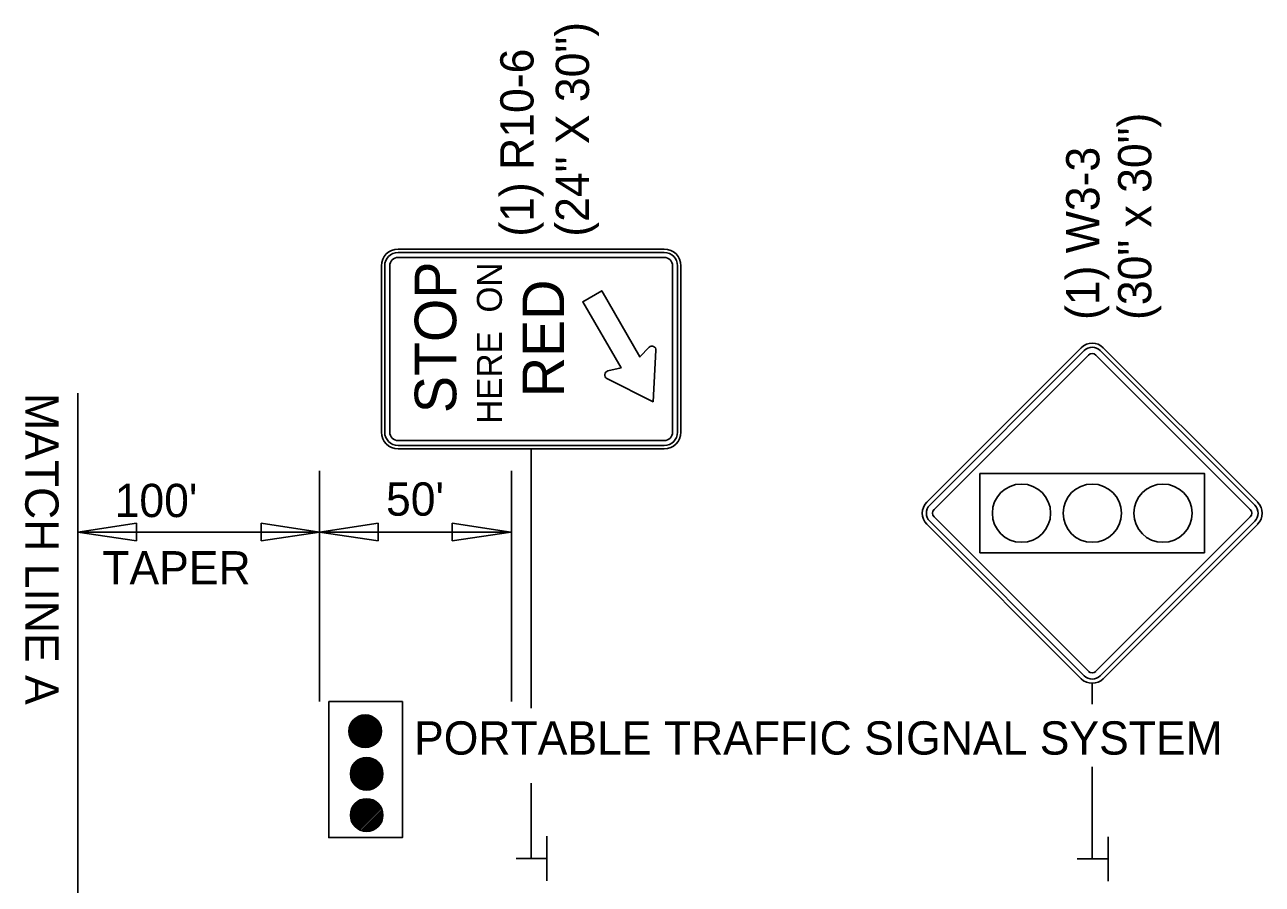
# Model space of a CAD drawing. Extents: x 1925873 to 1930787, y 596452 to 599617.
# Drawn here: x 1925900.5 to 1926123.6, y 596960 to 597114.9 of the extents above; entities that cross this region are included whole.
import ezdxf

# ---------------------------------------------------------------- set-up
doc = ezdxf.new("R2010")
doc.units = 0
for name, color, linetype in [('Default', 7, 'Continuous'), ('P_TC_Signs_Permanent', 7, 'Continuous'), ('R_Border', 7, 'Continuous')]:
    doc.layers.add(name, color=color, linetype=linetype)

msp = doc.modelspace()

# ---------------------------------------------------------------- linework, layer by layer
at = {"layer": 'Default'}
for p, q in [((1925910.09, 597048.55), (1925910.09, 596923.91)), ((1925953.65, 597034.54), (1925953.65, 596992.96)), ((1925988.22, 597034.54), (1925988.22, 596992.96)), ((1925910.09, 597023.5), (1925920.64, 597025.08)), ((1925920.64, 597025.08), (1925920.64, 597021.92)), ((1925943.11, 597021.92), (1925943.11, 597025.08)), ((1925943.11, 597025.08), (1925953.65, 597023.5)), ((1925953.65, 597023.5), (1925964.19, 597025.08)), ((1925964.19, 597025.08), (1925964.19, 597021.92)), ((1925977.56, 597021.92), (1925977.56, 597025.08)), ((1925977.56, 597025.08), (1925988.1, 597023.5)), ((1925920.64, 597021.92), (1925910.09, 597023.5)), ((1925910.09, 597023.5), (1925953.65, 597023.5)), ((1925953.65, 597023.5), (1925943.11, 597021.92)), ((1925953.65, 597023.5), (1925988.1, 597023.5)), ((1925964.19, 597021.92), (1925953.65, 597023.5)), ((1925988.1, 597023.5), (1925977.56, 597021.92)), ((1925958.92, 596987.65), (1925961.82, 596990.54)), ((1925958.93, 596987.47), (1925962, 596990.54)), ((1925958.93, 596987.84), (1925961.63, 596990.54)), ((1925958.94, 596987.3), (1925962.17, 596990.53)), ((1925958.96, 596987.14), (1925962.33, 596990.51)), ((1925958.96, 596988.04), (1925961.43, 596990.51)), ((1925958.99, 596986.99), (1925962.48, 596990.48)), ((1925959, 596988.26), (1925961.21, 596990.47)), ((1925959.02, 596986.84), (1925962.63, 596990.44)), ((1925959.06, 596986.7), (1925962.77, 596990.4)), ((1925959.07, 596988.51), (1925960.95, 596990.4)), ((1925959.11, 596986.57), (1925962.9, 596990.36)), ((1925959.16, 596986.44), (1925963.03, 596990.3)), ((1925959.18, 596988.81), (1925960.66, 596990.29)), ((1925959.22, 596986.31), (1925963.15, 596990.25)), ((1925959.28, 596986.2), (1925963.27, 596990.19)), ((1925959.35, 596986.08), (1925963.39, 596990.12)), ((1925959.4, 596989.21), (1925960.26, 596990.07)), ((1925959.42, 596985.97), (1925963.5, 596990.05)), ((1925959.49, 596985.86), (1925963.6, 596989.98)), ((1925959.57, 596985.76), (1925963.71, 596989.9)), ((1925959.65, 596985.66), (1925963.81, 596989.81)), ((1925959.74, 596985.57), (1925963.9, 596989.73)), ((1925959.83, 596985.48), (1925963.99, 596989.64)), ((1925959.93, 596985.39), (1925964.08, 596989.54)), ((1925960.02, 596985.31), (1925964.16, 596989.44)), ((1925960.13, 596985.23), (1925964.24, 596989.34)), ((1925960.23, 596985.16), (1925964.31, 596989.24)), ((1925960.34, 596985.09), (1925964.38, 596989.12)), ((1925960.46, 596985.02), (1925964.45, 596989.01)), ((1925960.58, 596984.96), (1925964.51, 596988.89)), ((1925960.7, 596984.9), (1925964.57, 596988.77)), ((1925960.83, 596984.85), (1925964.62, 596988.64)), ((1925960.96, 596984.8), (1925964.67, 596988.5)), ((1925961.1, 596984.76), (1925964.71, 596988.36)), ((1925961.25, 596984.73), (1925964.74, 596988.22)), ((1925961.4, 596984.7), (1925964.77, 596988.07)), ((1925961.56, 596984.68), (1925964.79, 596987.91)), ((1925961.73, 596984.66), (1925964.8, 596987.74)), ((1925961.91, 596984.66), (1925964.81, 596987.56)), ((1925962.1, 596984.67), (1925964.8, 596987.37)), ((1925962.3, 596984.69), (1925964.77, 596987.16)), ((1925962.53, 596984.74), (1925964.73, 596986.94)), ((1925962.78, 596984.81), (1925964.66, 596986.69)), ((1925963.07, 596984.92), (1925964.55, 596986.4)), ((1925963.47, 596985.14), (1925964.33, 596986)), ((1925959.19, 596979.99), (1925962.09, 596982.89)), ((1925959.2, 596979.81), (1925962.27, 596982.88)), ((1925959.2, 596980.18), (1925961.9, 596982.88)), ((1925959.21, 596979.64), (1925962.44, 596982.87)), ((1925959.23, 596979.48), (1925962.6, 596982.85)), ((1925959.23, 596980.38), (1925961.7, 596982.85)), ((1925959.26, 596979.33), (1925962.75, 596982.82)), ((1925959.27, 596980.6), (1925961.47, 596982.81)), ((1925959.29, 596979.18), (1925962.9, 596982.79)), ((1925959.33, 596979.04), (1925963.04, 596982.74)), ((1925959.34, 596980.85), (1925961.22, 596982.74)), ((1925959.38, 596978.91), (1925963.17, 596982.7)), ((1925959.43, 596978.78), (1925963.3, 596982.65)), ((1925959.45, 596981.15), (1925960.93, 596982.63)), ((1925959.49, 596978.66), (1925963.42, 596982.59)), ((1925959.55, 596978.54), (1925963.54, 596982.53)), ((1925959.62, 596978.42), (1925963.66, 596982.46)), ((1925959.67, 596981.55), (1925960.53, 596982.41)), ((1925959.69, 596978.31), (1925963.77, 596982.39)), ((1925959.76, 596978.2), (1925963.87, 596982.32)), ((1925959.84, 596978.1), (1925963.98, 596982.24)), ((1925959.92, 596978), (1925964.07, 596982.15)), ((1925960.01, 596977.91), (1925964.17, 596982.07)), ((1925960.1, 596977.82), (1925964.26, 596981.98)), ((1925960.19, 596977.73), (1925964.35, 596981.88)), ((1925960.29, 596977.65), (1925964.43, 596981.79)), ((1925960.4, 596977.57), (1925964.51, 596981.68)), ((1925960.5, 596977.5), (1925964.58, 596981.58)), ((1925960.61, 596977.43), (1925964.65, 596981.47)), ((1925960.73, 596977.36), (1925964.72, 596981.35)), ((1925960.85, 596977.3), (1925964.78, 596981.23)), ((1925960.97, 596977.24), (1925964.84, 596981.11)), ((1925961.1, 596977.19), (1925964.89, 596980.98)), ((1925961.23, 596977.14), (1925964.93, 596980.84)), ((1925961.37, 596977.1), (1925964.98, 596980.7)), ((1925961.52, 596977.07), (1925965.01, 596980.56)), ((1925961.67, 596977.04), (1925965.04, 596980.41)), ((1925961.83, 596977.02), (1925965.06, 596980.25)), ((1925962, 596977.01), (1925965.07, 596980.08)), ((1925962.18, 596977), (1925965.08, 596979.9)), ((1925962.37, 596977.01), (1925965.07, 596979.71)), ((1925962.57, 596977.04), (1925965.04, 596979.51)), ((1925962.8, 596977.08), (1925965, 596979.28)), ((1925963.05, 596977.15), (1925964.93, 596979.03)), ((1925963.34, 596977.26), (1925964.82, 596978.74)), ((1925963.74, 596977.48), (1925964.6, 596978.34)), ((1925959.19, 596972.47), (1925962.17, 596975.45)), ((1925959.2, 596972.29), (1925962.35, 596975.44)), ((1925959.2, 596972.65), (1925961.99, 596975.44)), ((1925959.21, 596972.85), (1925961.79, 596975.43)), ((1925959.22, 596972.13), (1925962.51, 596975.42)), ((1925959.24, 596971.97), (1925962.67, 596975.4)), ((1925959.25, 596973.06), (1925961.58, 596975.39)), ((1925959.27, 596971.82), (1925962.82, 596975.37)), ((1925959.3, 596973.3), (1925961.34, 596975.34)), ((1925959.31, 596971.68), (1925962.96, 596975.33)), ((1925959.35, 596971.54), (1925963.1, 596975.28)), ((1925959.39, 596973.57), (1925961.07, 596975.25)), ((1925959.4, 596971.41), (1925963.23, 596975.24)), ((1925959.46, 596971.28), (1925963.35, 596975.18)), ((1925959.52, 596971.16), (1925963.48, 596975.12)), ((1925959.55, 596973.91), (1925960.73, 596975.09)), ((1925959.58, 596971.05), (1925963.59, 596975.06)), ((1925959.65, 596970.93), (1925963.71, 596974.99)), ((1925959.72, 596970.82), (1925963.82, 596974.92)), ((1925959.8, 596970.72), (1925963.92, 596974.84)), ((1925959.88, 596970.62), (1925964.02, 596974.76)), ((1925959.96, 596970.52), (1925964.12, 596974.68)), ((1925960.05, 596970.43), (1925964.21, 596974.59)), ((1925960.14, 596970.34), (1925964.3, 596974.5)), ((1925960.24, 596970.26), (1925964.38, 596974.4)), ((1925960.34, 596970.18), (1925964.46, 596974.3)), ((1925960.44, 596970.1), (1925964.54, 596974.2)), ((1925960.55, 596970.03), (1925964.61, 596974.09)), ((1925960.66, 596969.96), (1925964.68, 596973.98)), ((1925960.78, 596969.89), (1925964.75, 596973.86)), ((1925960.9, 596969.83), (1925964.8, 596973.74)), ((1925961.16, 596969.73), (1925964.91, 596973.48)), ((1925961.3, 596969.69), (1925964.95, 596973.34)), ((1925961.44, 596969.65), (1925964.99, 596973.2)), ((1925961.59, 596969.61), (1925965.02, 596973.05)), ((1925961.74, 596969.59), (1925965.05, 596972.9)), ((1925961.91, 596969.57), (1925965.07, 596972.73)), ((1925962.08, 596969.56), (1925965.08, 596972.56)), ((1925962.26, 596969.57), (1925965.07, 596972.38)), ((1925962.46, 596969.58), (1925965.06, 596972.18)), ((1925962.67, 596969.61), (1925965.03, 596971.97)), ((1925962.9, 596969.67), (1925964.97, 596971.74)), ((1925963.17, 596969.75), (1925964.89, 596971.47)), ((1925963.5, 596969.9), (1925964.74, 596971.14)), ((1925964.07, 596970.29), (1925964.35, 596970.57)), ((1925994.64, 596968.67), (1925994.64, 596960.66)), ((1926095.79, 596968.57), (1926095.79, 596960.56)), ((1925994.53, 596964.69), (1925989.06, 596964.69)), ((1926095.67, 596964.59), (1926090.21, 596964.59))]:
    msp.add_line(p, q, dxfattribs=at)
msp.add_lwpolyline([(1925955.29, 596992.96), (1925968.58, 596992.96), (1925968.58, 596968.42), (1925955.29, 596968.42)], close=True, dxfattribs=at)
for centre in [(1925961.86, 596987.6), (1925962.13, 596979.94), (1925962.13, 596972.5)]:
    msp.add_circle(centre, 2.94, dxfattribs=at)
at = {"layer": 'P_TC_Signs_Permanent'}
for p, q in [((1925967.79, 597074.5), (1926015.79, 597074.5)), ((1925967.79, 597073.9), (1926015.79, 597073.9)), ((1925967.79, 597073), (1926015.79, 597073)), ((1925964.79, 597041.5), (1925964.79, 597071.5)), ((1925965.39, 597041.5), (1925965.39, 597071.5)), ((1925966.29, 597041.5), (1925966.29, 597071.5)), ((1926017.29, 597071.5), (1926017.29, 597041.5)), ((1926018.19, 597071.5), (1926018.19, 597041.5)), ((1926018.79, 597071.5), (1926018.79, 597041.5)), ((1926063.11, 597028.89), (1926090.95, 597056.73)), ((1926063.64, 597028.36), (1926091.48, 597056.2)), ((1926094.4, 597056.2), (1926122.24, 597028.36)), ((1926094.93, 597056.73), (1926122.77, 597028.89)), ((1926092.28, 597055.41), (1926064.43, 597027.56)), ((1926121.44, 597027.56), (1926093.6, 597055.41)), ((1926015.79, 597040), (1925967.79, 597040)), ((1926015.79, 597039.1), (1925967.79, 597039.1)), ((1926015.79, 597038.5), (1925967.79, 597038.5)), ((1926090.95, 596997.07), (1926063.11, 597024.91)), ((1926091.48, 596997.6), (1926063.64, 597025.44)), ((1926064.43, 597026.24), (1926092.28, 596998.4)), ((1926093.6, 596998.4), (1926121.44, 597026.24)), ((1926122.24, 597025.44), (1926094.4, 596997.6)), ((1926122.77, 597024.91), (1926094.93, 596997.07))]:
    msp.add_line(p, q, dxfattribs=at)
for points in [[(1926013.04, 597056.8), (1926011.4, 597055.06), (1926004.51, 597066.98), (1926001.1, 597065.01), (1926007.99, 597053.09), (1926005.62, 597052.54)], [(1926005.46, 597051.2), (1926013.78, 597047), (1926014.29, 597056.27)]]:
    msp.add_lwpolyline(points, dxfattribs=at)
msp.add_lwpolyline([(1926113.19, 597019.78), (1926113.19, 597034.03), (1926072.69, 597034.03), (1926072.69, 597019.78)], close=True, dxfattribs=at)
for centre in [(1926080.19, 597026.9), (1926092.94, 597026.9), (1926105.69, 597026.9)]:
    msp.add_circle(centre, 5.25, dxfattribs=at)
for centre, radius, start, end in [((1925967.79, 597071.5), 3, 90, 180), ((1926015.79, 597071.5), 3, 360, 90), ((1925967.79, 597071.5), 2.4, 90, 180), ((1925967.79, 597071.5), 1.5, 90, 180), ((1926015.79, 597071.5), 2.4, 360, 90), ((1926015.79, 597071.5), 1.5, 360, 90), ((1926013.57, 597056.31), 0.72, 356.857, 136.6377), ((1926092.94, 597054.74), 2.81, 45, 135), ((1926092.94, 597054.74), 2.06, 45, 135), ((1926092.94, 597054.74), 0.937, 45, 135), ((1926005.78, 597051.84), 0.72, 103.0349, 243.2286), ((1925967.79, 597041.5), 3, 180, 270), ((1925967.79, 597041.5), 2.4, 180, 270), ((1925967.79, 597041.5), 1.5, 180, 270), ((1926015.79, 597041.5), 3, 270, 360), ((1926015.79, 597041.5), 2.4, 270, 360), ((1926015.79, 597041.5), 1.5, 270, 360), ((1926065.1, 597026.9), 2.81, 135, 225), ((1926065.1, 597026.9), 2.06, 135, 225), ((1926065.1, 597026.9), 0.937, 135, 225), ((1926120.78, 597026.9), 0.938, 315, 45), ((1926120.78, 597026.9), 2.06, 315, 45), ((1926120.78, 597026.9), 2.81, 315, 45), ((1926092.94, 596999.06), 0.938, 225, 315), ((1926092.94, 596999.06), 2.81, 225, 315), ((1926092.94, 596999.06), 2.06, 225, 315)]:
    msp.add_arc(centre, radius, start, end, dxfattribs=at)
at = {"layer": 'R_Border'}
for p, q in [((1925991.79, 596991.75), (1925991.79, 597038.5)), ((1926092.94, 596992.48), (1926092.94, 596996.25)), ((1926092.94, 596964.59), (1926092.94, 596981.21)), ((1925991.79, 596964.69), (1925991.79, 596978.22))]:
    msp.add_line(p, q, dxfattribs=at)

# ---------------------------------------------------------------- texts
at = {"layer": 'Default'}
for s, rotation, p in [('MATCH LINE A', 270, (1925900.58, 597048.55)), (" 100' ", 360, (1925914.47, 597026.2)), ("50'", 360, (1925965.62, 597026.45)), ('TAPER', 360, (1925914.47, 597014.06)), ('PORTABLE TRAFFIC SIGNAL SYSTEM', 360, (1925970.68, 596983.39))]:
    msp.add_text(s, height=6, rotation=rotation, dxfattribs=at).set_placement(p)
at = {"layer": 'P_TC_Signs_Permanent'}
for s, height, p in [('STOP', 7.5, (1925978.29, 597044.94)), ('HERE  ON', 4.5, (1925986.51, 597043)), ('RED', 7.5, (1925997.73, 597047.83))]:
    msp.add_text(s, height=height, rotation=90, dxfattribs=at).set_placement(p)
at = {"layer": 'R_Border'}
for s, height, p in [('(24" X 30")', 5.9996, (1926002.23, 597076.74)), ('(1) R10-6', 6, (1925992.22, 597076.74)), ('(30" x 30")', 5.9996, (1926103.6, 597061.73)), ('(1) W3-3', 6, (1926094.24, 597061.73))]:
    msp.add_text(s, height=height, rotation=90, dxfattribs=at).set_placement(p)

doc.saveas('drawing.dxf')
